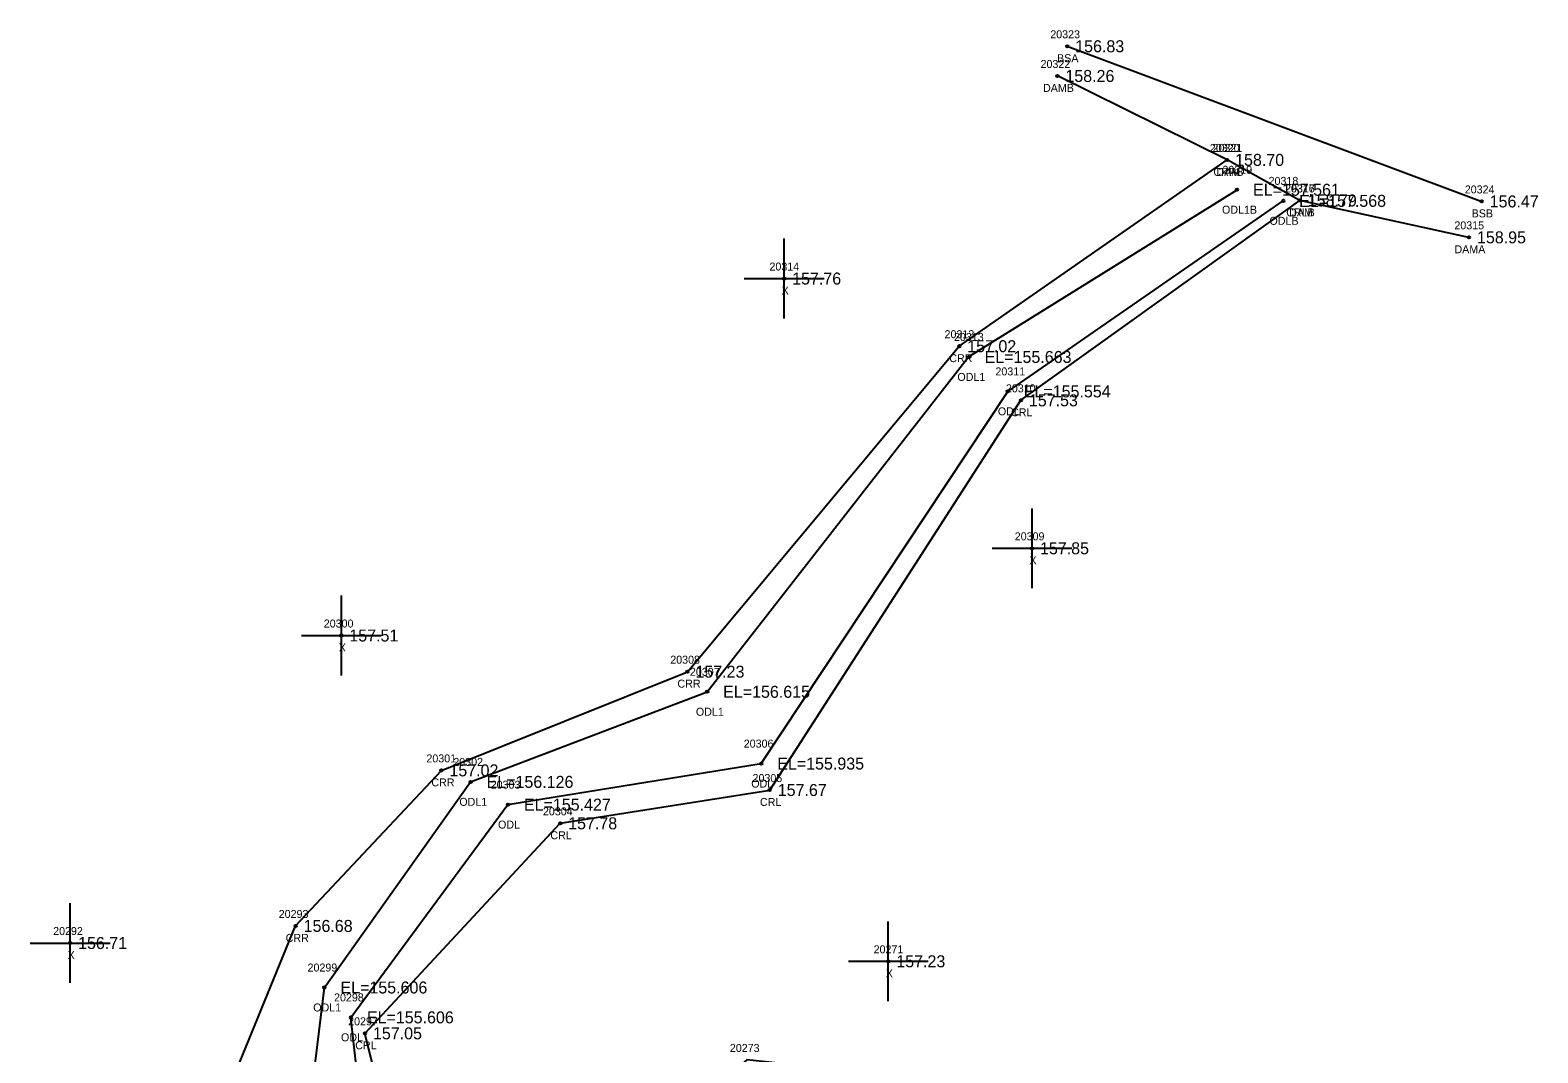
# Model space of a CAD drawing. Extents: x 2381545 to 2382928, y 1029933 to 1030589.
# Drawn here: x 2382148 to 2382336.8, y 1030461 to 1030589 of the extents above; entities that cross this region are included whole.
import ezdxf

# ---------------------------------------------------------------- set-up
doc = ezdxf.new("R2010")
doc.units = 0
for name, color, linetype in [('RD_DTM_BkLn2', 7, 'Continuous'), ('RD_DTM_BkLn_txCode', 7, 'Continuous'), ('RD_EX_Dam', 7, 'Continuous'), ('RD_EX_Dam_txCode', 7, 'Continuous'), ('RD_EX_H2O', 7, 'Continuous'), ('RD_EX_H2O_txCode', 7, 'Continuous'), ('RD_EX_Misc', 7, 'Continuous'), ('RD_EX_Misc_txCode', 7, 'Continuous'), ('RD_EX_TX_Dam_ELEV', 7, 'Continuous'), ('RD_EX_TX_H2O_ELEV', 7, 'Continuous'), ('RD_EX_TX_Misc_ELEV', 7, 'Continuous'), ('RD_SMD_Locator', 7, 'Continuous')]:
    doc.layers.add(name, color=color, linetype=linetype)

msp = doc.modelspace()

# ---------------------------------------------------------------- linework, layer by layer
at = {"layer": 'RD_DTM_BkLn2'}
msp.add_line((2382277.84, 1030587.03), (2382329.73, 1030567.6), dxfattribs=at)
at = {"layer": 'RD_EX_Dam'}
msp.add_lwpolyline([(2382328.14, 1030563.1), (2382306.96, 1030567.72), (2382297.86, 1030572.8), (2382276.61, 1030583.31)], dxfattribs=at)
at = {"layer": 'RD_EX_H2O'}
for points in [[(2382160.73, 1030399.39), (2382154.77, 1030412.15), (2382181.24, 1030476.87), (2382199.49, 1030496.35), (2382230.29, 1030508.71), (2382264.32, 1030549.47), (2382297.86, 1030572.8)], [(2382213.26, 1030387.6), (2382208.44, 1030395.24), (2382205.81, 1030395.94), (2382192.08, 1030400.18), (2382164.48, 1030404.11), (2382160.24, 1030410.13), (2382182.19, 1030447.29), (2382184.85, 1030469.16), (2382203.14, 1030494.91), (2382232.76, 1030506.19), (2382265.5, 1030548.12), (2382299.1, 1030569.06)], [(2382220.88, 1030388.74), (2382215.51, 1030402.22), (2382206.23, 1030402.16), (2382191.8, 1030402.16), (2382166.42, 1030409.62), (2382190.19, 1030447.26), (2382188.16, 1030465.42), (2382207.82, 1030492.06), (2382239.53, 1030497.2), (2382270.4, 1030543.81), (2382304.88, 1030567.67)], [(2382228.76, 1030407.08), (2382250.84, 1030437.74), (2382249.44, 1030458.83), (2382237.72, 1030460.09), (2382220.83, 1030445.27), (2382209.26, 1030431.73), (2382194.07, 1030410.53), (2382182.03, 1030416.61), (2382193.97, 1030447.24), (2382189.92, 1030463.42), (2382214.36, 1030489.72), (2382240.6, 1030493.89), (2382272.04, 1030542.69), (2382306.96, 1030567.72)]]:
    msp.add_lwpolyline(points, dxfattribs=at)
at = {"layer": 'RD_EX_Misc'}
for p, q in [((2382242.4, 1030552.94), (2382242.4, 1030562.94)), ((2382237.4, 1030557.94), (2382247.4, 1030557.94)), ((2382273.43, 1030519.16), (2382273.43, 1030529.16)), ((2382268.43, 1030524.16), (2382278.43, 1030524.16)), ((2382186.96, 1030508.24), (2382186.96, 1030518.24)), ((2382181.96, 1030513.24), (2382191.96, 1030513.24)), ((2382153, 1030469.73), (2382153, 1030479.73)), ((2382255.44, 1030467.44), (2382255.44, 1030477.44)), ((2382148, 1030474.73), (2382158, 1030474.73)), ((2382250.44, 1030472.44), (2382260.44, 1030472.44))]:
    msp.add_line(p, q, dxfattribs=at)
at = {"layer": 'RD_SMD_Locator'}
for centre in [(2382277.84, 1030587.03), (2382276.61, 1030583.31), (2382297.86, 1030572.8), (2382297.86, 1030572.8), (2382299.1, 1030569.06), (2382304.88, 1030567.67), (2382306.96, 1030567.72), (2382306.96, 1030567.72), (2382329.73, 1030567.6), (2382328.14, 1030563.1), (2382242.4, 1030557.94), (2382264.32, 1030549.47), (2382265.5, 1030548.12), (2382270.4, 1030543.81), (2382272.04, 1030542.69), (2382273.43, 1030524.16), (2382186.96, 1030513.24), (2382230.29, 1030508.71), (2382232.76, 1030506.19), (2382239.53, 1030497.2), (2382199.49, 1030496.35), (2382203.14, 1030494.91), (2382240.6, 1030493.89), (2382207.82, 1030492.06), (2382214.36, 1030489.72), (2382181.24, 1030476.87), (2382153, 1030474.73), (2382255.44, 1030472.44), (2382184.85, 1030469.16), (2382188.16, 1030465.42), (2382189.92, 1030463.42)]:
    msp.add_circle(centre, 0.15, dxfattribs=at)

# ---------------------------------------------------------------- texts
at = {"layer": 'RD_DTM_BkLn_txCode'}
for s, p in [('20323', (2382275.72, 1030588.03)), ('BSA', (2382276.57, 1030585.03)), ('20324', (2382327.61, 1030568.6)), ('BSB', (2382328.47, 1030565.6))]:
    msp.add_text(s, height=1, dxfattribs=at).set_placement(p)
at = {"layer": 'RD_EX_Dam_txCode'}
for s, p in [('20322', (2382274.5, 1030584.31)), ('DAMB', (2382274.81, 1030581.31)), ('20321', (2382296.03, 1030573.8)), ('DAM', (2382296.53, 1030570.8)), ('20317', (2382305.12, 1030568.72)), ('DAM', (2382305.63, 1030565.72)), ('20315', (2382326.31, 1030564.1)), ('DAMA', (2382326.32, 1030561.1))]:
    msp.add_text(s, height=1, dxfattribs=at).set_placement(p)
at = {"layer": 'RD_EX_H2O_txCode'}
for s, p in [('20320', (2382295.7, 1030573.8)), ('CRRB', (2382296.14, 1030570.8)), ('20319', (2382297.27, 1030571.06)), ('20318', (2382303.05, 1030569.67)), ('20316', (2382305.1, 1030568.72)), ('ODL1B', (2382297.22, 1030566.06)), ('CRLB', (2382305.26, 1030565.72)), ('ODLB', (2382303.16, 1030564.67)), ('20312', (2382262.48, 1030550.47)), ('20313', (2382263.66, 1030550.12)), ('CRR', (2382263.07, 1030547.47)), ('ODL1', (2382264.09, 1030545.12)), ('20311', (2382268.85, 1030545.81)), ('20310', (2382270.16, 1030543.69)), ('ODL', (2382269.16, 1030540.81)), ('CRL', (2382270.81, 1030540.69)), ('20308', (2382228.14, 1030509.71)), ('20307', (2382230.6, 1030508.19)), ('CRR', (2382229.04, 1030506.71)), ('ODL1', (2382231.35, 1030503.19)), ('20306', (2382237.34, 1030499.2)), ('20301', (2382197.61, 1030497.35)), ('20302', (2382200.98, 1030496.91)), ('CRR', (2382198.23, 1030494.35)), ('20303', (2382205.66, 1030494.06)), ('ODL', (2382238.28, 1030494.2)), ('20305', (2382238.44, 1030494.89)), ('ODL1', (2382201.73, 1030491.91)), ('CRL', (2382239.37, 1030491.89)), ('20304', (2382212.2, 1030490.72)), ('ODL', (2382206.58, 1030489.06)), ('CRL', (2382213.13, 1030487.72)), ('20293', (2382179.12, 1030477.87)), ('CRR', (2382179.99, 1030474.87)), ('20299', (2382182.73, 1030471.16)), ('20298', (2382186.05, 1030467.42)), ('ODL1', (2382183.44, 1030466.16)), ('20297', (2382187.81, 1030464.42)), ('ODL', (2382186.92, 1030462.42)), ('CRL', (2382188.7, 1030461.42)), ('20273', (2382235.6, 1030461.09))]:
    msp.add_text(s, height=1, dxfattribs=at).set_placement(p)
at = {"layer": 'RD_EX_Misc_txCode'}
for s, p in [('20314', (2382240.56, 1030558.94)), ('X', (2382242.08, 1030555.94)), ('20309', (2382271.27, 1030525.16)), ('X', (2382273.11, 1030522.16)), ('20300', (2382184.76, 1030514.24)), ('X', (2382186.64, 1030511.24)), ('20292', (2382150.88, 1030475.73)), ('20271', (2382253.6, 1030473.44)), ('X', (2382152.69, 1030472.73)), ('X', (2382255.12, 1030470.44))]:
    msp.add_text(s, height=1, dxfattribs=at).set_placement(p)
at = {"layer": 'RD_EX_TX_Dam_ELEV'}
for s, p in [('158.26', (2382277.61, 1030582.56)), ('158.70', (2382298.86, 1030572.05)), ('158.79', (2382307.96, 1030566.97)), ('158.95', (2382329.14, 1030562.35))]:
    msp.add_text(s, height=1.5, dxfattribs=at).set_placement(p)
at = {"layer": 'RD_EX_TX_H2O_ELEV'}
for s, p in [('158.70', (2382298.86, 1030572.05)), ('EL=157.561', (2382301.1, 1030568.31)), ('EL=157.568', (2382306.88, 1030566.92)), ('158.79', (2382307.96, 1030566.97)), ('157.02', (2382265.32, 1030548.72)), ('EL=155.663', (2382267.5, 1030547.37)), ('EL=155.554', (2382272.4, 1030543.06)), ('157.53', (2382273.04, 1030541.94)), ('157.23', (2382231.29, 1030507.96)), ('EL=156.615', (2382234.76, 1030505.44)), ('157.02', (2382200.49, 1030495.6)), ('EL=155.935', (2382241.53, 1030496.45)), ('EL=156.126', (2382205.14, 1030494.16)), ('EL=155.427', (2382209.82, 1030491.31)), ('157.67', (2382241.6, 1030493.14)), ('157.78', (2382215.36, 1030488.97)), ('156.68', (2382182.24, 1030476.12)), ('EL=155.606', (2382186.85, 1030468.41)), ('EL=155.606', (2382190.16, 1030464.67)), ('157.05', (2382190.92, 1030462.67))]:
    msp.add_text(s, height=1.5, dxfattribs=at).set_placement(p)
at = {"layer": 'RD_EX_TX_Misc_ELEV'}
for s, p in [('156.83', (2382278.84, 1030586.28)), ('156.47', (2382330.73, 1030566.85)), ('157.76', (2382243.4, 1030557.19)), ('157.85', (2382274.43, 1030523.41)), ('157.51', (2382187.96, 1030512.49)), ('156.71', (2382154, 1030473.98)), ('157.23', (2382256.44, 1030471.69))]:
    msp.add_text(s, height=1.5, dxfattribs=at).set_placement(p)

doc.saveas('drawing.dxf')
